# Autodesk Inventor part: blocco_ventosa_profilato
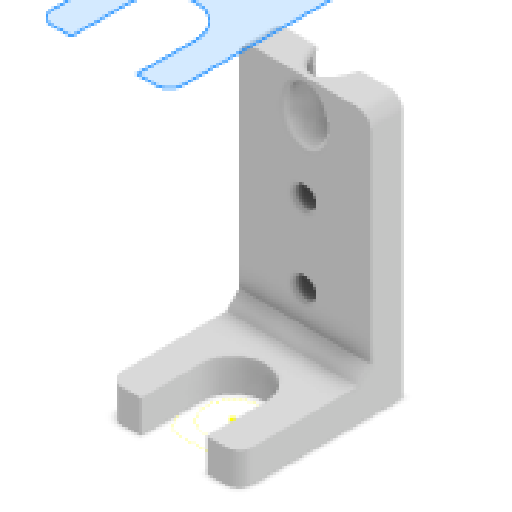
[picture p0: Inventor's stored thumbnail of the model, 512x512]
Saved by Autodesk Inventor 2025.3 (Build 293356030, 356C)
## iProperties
Created: 2026-03
Part Number: blocco_ventosa_profilato
Material: Generico
Document SubType Name: Modeling
Designer: Ryzen5700u
Density: 1 g/cm^3
Appearance: Default
Author: Ryzen5700u
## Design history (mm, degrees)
sketch "Schizzo1"
  geometry: L1 (10, 16)-(-10, 16); L2 (-10, 16)-(-10, -16); L3 (-10, -16)-(10, -16); L4 (10, -16)-(10, 16); L5 (10, 16)-(-10, -16); L6 (-10, 16)-(10, -16); L7 (10, 0)-(-10, 0); L8 (10, 9)-(-10, 9); L9 (5, 0)-(5, 9); L10 (-5, 0)-(-5, 9); A1 r 5 centre (0, 0) between (5, 0) and (-5, 0); 4 further points
  constraints: 20 end point, 6 point on line, 5 midpoint, 4 perpendicular, 2 parallel, 2 point on circle, 1 centre point, 1 coincident, 1 horizontal, 1 tangent
  dimensions: "d0" = 10 diameter of A1; "d1" = 20 distance of L3.end L2.end; "d2" = 32 distance of L2.end L1.end; "d17" = 9 distance from line of point (0, 0) L8
extrude "Estrusione1" new body sketch "Schizzo1" distance "d3" = 6; taper "d4" = 0 deg
sketch "Schizzo2"
  geometry: L1 (-10, 16)-(10, 16); L2 (10, 16)-(10, 11); L3 (10, 11)-(-10, 11); L4 (-10, 11)-(-10, 16); 8 further points
  constraints: 8 end point, 2 parallel, 1 horizontal, 1 perpendicular, 3 other
  dimensions: "d5" = 5 distance of L1.end L2.end
extrude "Estrusione2" join sketch "Schizzo2" distance "d6" = 35; taper "d7" = 0 deg
sketch "Schizzo3"
  geometry: L1 (0, 35)-(20, 35) reference; L2 (3, 0)-(14, 0) reference; L3 (10, 35)-(10, -6); 4 further points
  constraints: 2 end point, 2 point on line, 1 midpoint, 1 perpendicular
  dimensions: "d8" = 16 distance from line of L1 point (10, 19); "d9" = 12 distance of point (10, 19) point (10, 7)
hole "Foro1" sketch "Schizzo3" at (10, 19), (10, 7) diameter "d10" = 3.4; stored, may be unused: countersink angle "d14" = 90 deg, drill point angle "d16" = 118 deg; dims "d11" = 6, "d12" = 6.5, "d13" = 3.4, "d15" = 8
fillet "Raccordo1" dims "d18" = 2
chamfer "Smusso1" distance "d19" = 2; stored, may be unused: second distance "d20" = 2, angle "d21" = 45 deg
sketch "Schizzo4"
  geometry: L1 (0, 0)-(20, 0) reference; L2 (10, 0)-(10, -2); C1 r 0.5 at (10, -2); 3 further points
  constraints: 2 end point, 1 centre point, 1 coincident, 1 midpoint, 1 vertical
  dimensions: "d22" = 2 distance of L2.start L2.end; "d23" = 1 diameter of C1
extrude "Estrusione3" cut sketch "Schizzo4" distance "d24" = 30; taper "d25" = 0 deg
fillet "Raccordo3" dims "d27" = 2
node "Piano di lavoro1"
sketch "Schizzo5"
  geometry: L1 (3, -27.032)-(-13, -27.032) reference; L2 (-5, -27.032)-(-5, -22.532); 2 further points
  constraints: 2 end point, 1 coincident, 1 midpoint, 1 vertical
  dimensions: "d29" = -4.5 distance of L2.start L2.end
hole "Foro2" sketch "Schizzo5" at (-5, -22.532) diameter "d30" = 6.5; stored, may be unused: countersink angle "d34" = 90 deg, drill point angle "d36" = 118 deg; dims "d31" = 6, "d32" = 4, "d33" = 2, "d35" = 8
fillet "Raccordo4" dims "d37" = 0.5
sketch "Schizzo6"
  geometry: L1 (3.464, 6)-(-3.464, 6) reference; L2 (-3.464, 6)-(-6.928, 0) reference; L3 (-6.928, 0)-(-3.464, -6) reference; L4 (-3.464, -6)-(3.464, -6) reference; L5 (3.464, -6)-(6.928, 0) reference; L6 (6.928, 0)-(3.464, 6) reference; L7 (-3.551, -6.15)-(-7.101, 0); L8 (-7.101, 0)-(-3.551, 6.15); L9 (-3.551, 6.15)-(3.551, 6.15); L10 (3.551, 6.15)-(7.101, 0); L11 (7.101, 0)-(3.551, -6.15); L12 (3.551, -6.15)-(-3.551, -6.15); C1 r 4 at (0, 0) reference; 1 further point
  constraints: 12 end point, 5 other
  dimensions: "d39" = 0.15 distance between parallel lines of L3 L7
extrude "Estrusione4" cut sketch "Schizzo6" distance "d40" = 2; taper "d41" = 0 deg
node "Solido1"
node "Riferimento1"
other parameters: "d28" = -35 deg
